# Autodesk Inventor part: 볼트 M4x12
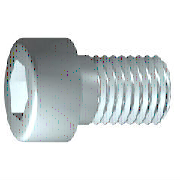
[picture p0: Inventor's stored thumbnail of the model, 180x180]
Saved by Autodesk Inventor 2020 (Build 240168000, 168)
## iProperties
Created: 2012-02
Part Number: 볼트 M4x12
Material: 강철, 연강
Description: 6각 소켓 머리 캡 나사
Document SubType Name: Modeling
Standard: ISO 4762
Designer: mdu-01
Standard Revision: Fourth edition 2004-03-01
Standards Organization: ISO
Language: ko-KR
Size Designation: M4 x 12
Categories: <MemberInstance><Categories><Category DisplayName="조임쇠" InternalName="e4da775c-781d-43d5-af7c-5136215cf5a6" Mnemonic="FSTN"><Category DisplayName="볼트" InternalN
Density: 7.86 g/cm^3
Appearance: 강철
Mass: 2.23465 g
Surface Area: 3.30853 cm^2
Volume: 0.284306 cm^3
IsCustomPart: 1
Author: mdu-01
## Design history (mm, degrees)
sketch "스케치1"
  geometry: L1 (-1, 0)-(12, 0); L2 (12, 0)-(12, 2); L3 (12, 2)-(1.75, 2); L4 (1.75, 2)-(1.32, 2); L5 (1.32, 2)-(0, 2); L6 (0, 2)-(0, 3.5); L7 (0, 3.5)-(-4, 3.5); L8 (-4, 3.5)-(-4, 1.732); L9 (-4, 1.732)-(-2, 1.732); L10 (-2, 1.732)-(-1, 0); L11 (-7.2, 0)-(15.2, 0) reference; L12 (0, -0.7)-(0, 4.2) reference; L13 (1.75, 2)-(0, 2)
  constraints: 22 end point, 6 parallel, 2 collinear, 2 perpendicular, 1 horizontal, 1 point on line
  dimensions: "d1" = 10.25 distance from line of L3.end L2 (= GEL); "d2" = 0.42952 distance of L4.end L3.end (computed from GAL); "d3" = 4 distance between parallel lines of L8 L6 (= KOH); "d4" = 2 distance of L8.end L9.end (= INTI); "d5" = 60 deg angle of L10 L1; "d6" = 4 diameter of L3 L1 (= GD); "d7" = 4 diameter of L5 L1 (= BDM); "d8" = 3.4641 diameter of L9 L1 (= 1.1547 x SW); "d9" = 7 diameter of L7 L1 (= KOD); "d26" = 12 distance between parallel lines of L12 L2 (= NLG)
revolve "본체" sketch "스케치1" stored, may be unused: angle "d10" = 90 deg
sketch "스케치2"
  geometry: L1 (0, -4.9)-(0, 4.9) reference; L2 (-4.9, 0)-(4.9, 0) reference; L3 (1.732, 0)-(0.866, -1.5); L4 (0.866, -1.5)-(-0.866, -1.5); L5 (-0.866, -1.5)-(-1.732, 0); L6 (-1.732, 0)-(-0.866, 1.5); L7 (-0.866, 1.5)-(0.866, 1.5); L8 (0.866, 1.5)-(1.732, 0); 2 further points
  constraints: 12 end point, 1 coincident, 1 horizontal alignment, 1 point on line, 12 other
extrude "슬롯" join sketch "스케치2" stored distance "d11" = 10; taper "d12" = 0 deg
workplane "Work Plane1"
fillet "Fillet2" dims "d30" = 0.1 (= R)
body "Solid1"
fillet "모깎기1" dims "d17" = 0.4 (= RR)
feature "스레드" dims "d13" = 10.25 (= GEL), "d14" = 0
chamfer "모따기1" distance "d15" = 0.42941 (= -0.5 x SPD + 0.5 x GD); stored, may be unused: second distance "d16" = 0.42941 (= GUL), angle "d27" = 45 deg
other parameters: "GD" = 4 [user parameter; used in 2 equation terms], "NLG" = 12 [user parameter; used in 1 equation term], "GEL" = 10.25 [user parameter; used in 2 equation terms], "KOD" = 7 [user parameter; used in 1 equation term], "KOH" = 4 [user parameter; used in 1 equation term], "INTI" = 2 [user parameter; used in 1 equation term], "GAL" = 0.42941 (= 0.61345 x PTC) [user parameter; used in 1 equation term], "GUL" = 0.42941 (= 0.61345 x PTC) [user parameter; used in 1 equation term], "BDM" = 4 (= NND) [user parameter; used in 1 equation term], "SW" = 3 [user parameter; used in 2 equation terms], "RR" = 0.4 [user parameter; used in 1 equation term], "SPD" = 3.14117 (= NND - 1.2269 x PTC) [user parameter; used in 1 equation term], "d19" = 0, "d28" = 0, "d29" = 0, "R" = 0.1 [user parameter; used in 1 equation term], "TOA" = 30 deg [user parameter], "GD1" = 3.14117 (= THREADDIA - 1.2269 x PTC) [user parameter], "THREADDIA" = 4 [user parameter; used in 1 equation term], "FAWI" = 45 deg [user parameter], "TPU" = 14.28571 (computed from PTC) [user parameter], "PTC" = 0.7 [user parameter; used in 5 equation terms], "NND" = 4 [user parameter; used in 2 equation terms], "E0" = 3.465 (= 1.155 x SW) [user parameter]
